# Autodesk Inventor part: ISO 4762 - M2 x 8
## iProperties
Created: 2008-01
Part Number: ISO 4762 - M2 x 8
Material: Stainless Steel, 440C
Description: Hexagon Socket Head Cap Screw
Document SubType Name: Modeling
Standard: ISO 4762
Designer: latalom
Standard Revision: Fourth edition 2004-03-01
Standards Organization: ISO
Language: en-US
Size Designation: M2 x 8
Categories: <MemberInstance><Categories><Category DisplayName="Fasteners" InternalName="e4da775c-781d-43d5-af7c-5136215cf5a6" Mnemonic="FSTN"><Category DisplayName="Bolts"
Density: 7.75 g/cm^3
IsCustomPart: 0
Author: latalom
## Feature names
1. Body [Revolution]
2. Slot [Extrusion]
3. Fillet1
4. Chamfer1
5. Fillet2
